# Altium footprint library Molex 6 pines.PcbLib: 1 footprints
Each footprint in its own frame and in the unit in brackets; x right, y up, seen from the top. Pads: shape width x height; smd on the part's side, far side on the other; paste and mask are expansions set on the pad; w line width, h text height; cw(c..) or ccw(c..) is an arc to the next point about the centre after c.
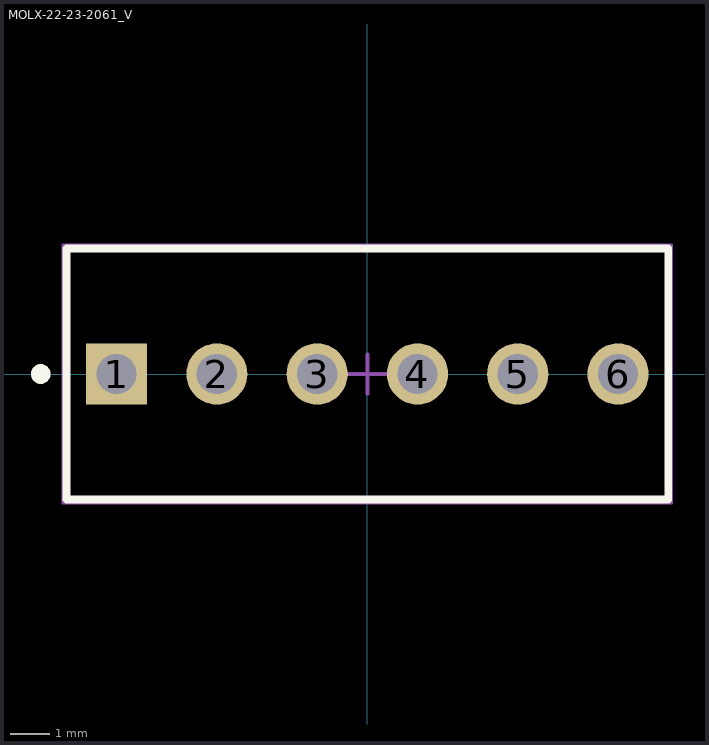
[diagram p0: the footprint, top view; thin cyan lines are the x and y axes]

## MOLX-22-23-2061_V [mm] "THD, 6-Leads, Body 15.24x6.35mm, Pitch 2.54mm"
height 10.67
pads (6):
  rect 1.55x1.55 hole 1.02: 1(-6.35,0)
  round 1.55 hole 1.02: 2(-3.81,0) 3(-1.27,0) 4(1.27,0) 5(3.81,0) 6(6.35,0)
Top Overlay:
  circle w0.25: c-8.27,0 r0.125
  lines w0.2: -7.62,-3.175 -7.62,3.175 7.62,3.175 7.62,-3.175 -7.62,-3.175
Mechanical 13:
  lines w0.1: -7.62,-3.175 -7.62,3.175 7.62,3.175 7.62,-3.175 -7.62,-3.175
Mechanical 15:
  lines w0.05: -7.72,-3.275 -7.72,3.275 7.72,3.275 7.72,-3.275 -7.72,-3.275
  lines w0.1: -0.5,0 0.5,0 ; 0,-0.5 0,0.5
3D body "022232061.stp": height 10.67, standoff -3.56, extent -7.544,-3.251 7.544,3.099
